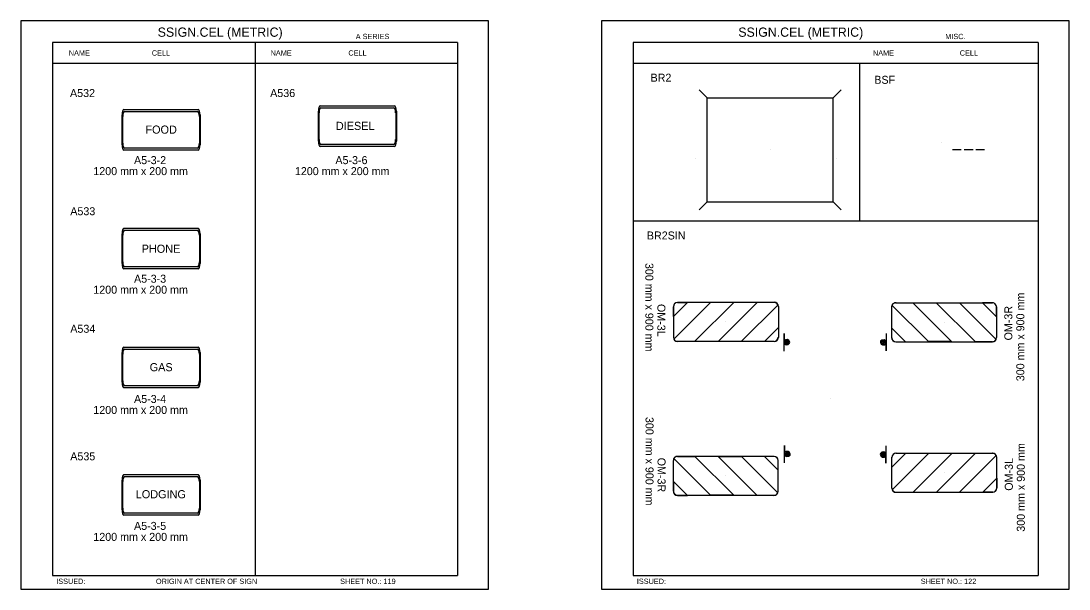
# Model space of a CAD drawing. Extents: x -12 to 6962, y -3756 to 679.
# Drawn here: x 237.8 to 630.7, y -2779.8 to -2566.7 of the extents above; entities that cross this region are included whole.
import ezdxf

# ---------------------------------------------------------------- set-up
doc = ezdxf.new("R2010")
doc.units = 0
for name, color, linetype in [('Level 1', 7, 'Continuous'), ('Level 2', 7, 'Continuous'), ('Level 3', 7, 'Continuous'), ('Level 60', 7, 'Continuous')]:
    doc.layers.add(name, color=color, linetype=linetype)

msp = doc.modelspace()

# ---------------------------------------------------------------- linework, layer by layer
at = {"layer": 'Level 1'}
for p, q in [((401.39, -2574.77), (249.64, -2574.77)), ((249.64, -2574.77), (249.64, -2774.77)), ((325.51, -2574.77), (325.51, -2774.77)), ((401.39, -2574.77), (401.39, -2774.77)), ((619.06, -2574.77), (467.3, -2574.77)), ((467.3, -2574.77), (467.3, -2774.77)), ((619.06, -2574.77), (619.06, -2774.77)), ((401.39, -2582.69), (249.64, -2582.69)), ((619.06, -2582.69), (467.3, -2582.69)), ((552.07, -2582.69), (552.07, -2641.89)), ((494.96, -2595.58), (491.98, -2592.6)), ((542.3, -2595.58), (545.28, -2592.6)), ((494.96, -2634.61), (494.96, -2595.58)), ((494.96, -2595.58), (542.3, -2595.58)), ((528.1, -2595.58), (538.37, -2595.58)), ((542.3, -2634.61), (542.3, -2595.58)), ((276.39, -2599.95), (304.18, -2599.95)), ((276.6, -2600.7), (303.97, -2600.7)), ((349.25, -2611.78), (349.25, -2600.61)), ((349.98, -2598.57), (377.78, -2598.57)), ((350.2, -2599.33), (377.56, -2599.33)), ((378.51, -2600.61), (378.51, -2611.78)), ((275.66, -2613.16), (275.66, -2601.98)), ((275.93, -2612.56), (275.93, -2602.58)), ((304.64, -2602.58), (304.64, -2612.56)), ((304.91, -2601.98), (304.91, -2613.16)), ((349.52, -2611.18), (349.52, -2601.21)), ((378.24, -2601.21), (378.24, -2611.18)), ((290.28, -2607.57), (290.28, -2607.57)), ((290.28, -2607.57), (290.28, -2607.57)), ((363.88, -2606.19), (363.88, -2606.19)), ((363.88, -2606.19), (363.88, -2606.19)), ((582.93, -2612.43), (582.93, -2612.43)), ((304.18, -2615.19), (276.39, -2615.19)), ((303.97, -2614.43), (276.6, -2614.43)), ((377.78, -2613.81), (349.98, -2613.81)), ((377.56, -2613.06), (350.2, -2613.06)), ((518.68, -2615), (518.68, -2615)), ((587.06, -2614.97), (590.23, -2614.97)), ((591.32, -2614.97), (594.76, -2614.97)), ((595.8, -2614.97), (598.97, -2614.97)), ((490.52, -2618.45), (490.52, -2618.45)), ((543.45, -2618.45), (543.45, -2618.45)), ((491.98, -2637.59), (494.96, -2634.61)), ((494.96, -2634.61), (542.3, -2634.61)), ((528.1, -2634.61), (539.68, -2634.61)), ((545.28, -2637.59), (542.3, -2634.61)), ((619.06, -2641.89), (467.3, -2641.89)), ((275.66, -2657.71), (275.66, -2646.53)), ((275.93, -2657.11), (275.93, -2647.13)), ((276.39, -2644.5), (304.18, -2644.5)), ((276.6, -2645.25), (303.97, -2645.25)), ((304.64, -2647.13), (304.64, -2657.11)), ((304.91, -2646.53), (304.91, -2657.71)), ((290.28, -2652.12), (290.28, -2652.12)), ((290.28, -2652.12), (290.28, -2652.12)), ((304.18, -2659.74), (276.39, -2659.74)), ((303.97, -2658.99), (276.6, -2658.99)), ((487.65, -2672.29), (482.38, -2677.55)), ((482.38, -2673.85), (482.38, -2685.35)), ((482.38, -2677.55), (482.38, -2673.91)), ((496.29, -2672.35), (482.58, -2686.07)), ((483.88, -2672.29), (487.65, -2672.29)), ((520.28, -2672.29), (483.94, -2672.29)), ((490.44, -2686.85), (505, -2672.35)), ((505, -2672.35), (496.29, -2672.35)), ((513.71, -2672.35), (499.22, -2686.85)), ((507.93, -2686.85), (521.58, -2673.2)), ((520.02, -2672.29), (513.71, -2672.35)), ((521.71, -2673.85), (521.71, -2685.35)), ((564.18, -2674), (564.18, -2685.51)), ((577.96, -2687), (564.31, -2673.35)), ((565.61, -2672.44), (601.95, -2672.44)), ((565.87, -2672.44), (572.18, -2672.51)), ((572.18, -2672.51), (586.67, -2687)), ((580.89, -2672.51), (589.6, -2672.51)), ((595.45, -2687), (580.89, -2672.51)), ((589.6, -2672.51), (603.31, -2686.22)), ((598.24, -2672.44), (603.51, -2677.71)), ((602.01, -2672.44), (598.24, -2672.44)), ((603.51, -2674), (603.51, -2685.51)), ((603.51, -2677.71), (603.51, -2674.07)), ((502.08, -2679.6), (502.08, -2679.6)), ((583.82, -2679.75), (583.82, -2679.75)), ((516.51, -2686.91), (521.71, -2681.71)), ((521.71, -2681.71), (521.71, -2685.35)), ((569.38, -2687.07), (564.18, -2681.87)), ((564.18, -2681.87), (564.18, -2685.51)), ((483.88, -2686.91), (490.44, -2686.85)), ((520.15, -2686.91), (483.94, -2686.91)), ((499.22, -2686.85), (507.93, -2686.85)), ((520.08, -2686.91), (516.51, -2686.91)), ((521.71, -2685.35), (521.71, -2685.42)), ((564.18, -2685.51), (564.18, -2685.57)), ((565.74, -2687.07), (601.95, -2687.07)), ((565.81, -2687.07), (569.38, -2687.07)), ((586.67, -2687), (577.96, -2687)), ((602.01, -2687.07), (595.45, -2687)), ((275.66, -2702.26), (275.66, -2691.08)), ((276.39, -2689.05), (304.18, -2689.05)), ((276.6, -2689.81), (303.97, -2689.81)), ((304.91, -2691.08), (304.91, -2702.26)), ((275.93, -2701.66), (275.93, -2691.68)), ((304.64, -2691.68), (304.64, -2701.66)), ((290.28, -2696.67), (290.28, -2696.67)), ((290.28, -2696.67), (290.28, -2696.67)), ((304.18, -2704.29), (276.39, -2704.29)), ((303.97, -2703.54), (276.6, -2703.54)), ((541.15, -2708.25), (541.15, -2708.25)), ((483.84, -2730.06), (490.4, -2730.12)), ((520.11, -2730.06), (483.9, -2730.06)), ((490.4, -2730.12), (504.96, -2744.62)), ((513.67, -2744.62), (499.18, -2730.12)), ((499.18, -2730.12), (507.89, -2730.12)), ((507.89, -2730.12), (521.54, -2743.78)), ((520.04, -2730.06), (516.47, -2730.06)), ((516.47, -2730.06), (521.67, -2735.26)), ((569.45, -2728.9), (564.25, -2734.1)), ((564.25, -2730.46), (564.25, -2730.4)), ((564.25, -2741.97), (564.25, -2730.46)), ((564.25, -2734.1), (564.25, -2730.46)), ((578.03, -2728.97), (564.38, -2742.62)), ((565.81, -2728.9), (602.02, -2728.9)), ((565.88, -2728.9), (569.45, -2728.9)), ((572.25, -2743.46), (586.74, -2728.97)), ((586.74, -2728.97), (578.03, -2728.97)), ((595.52, -2728.97), (580.96, -2743.46)), ((589.67, -2743.46), (603.38, -2729.75)), ((602.08, -2728.9), (595.52, -2728.97)), ((603.58, -2741.97), (603.58, -2730.46)), ((482.34, -2743.12), (482.34, -2731.62)), ((496.25, -2744.62), (482.54, -2730.91)), ((521.67, -2731.62), (521.67, -2731.55)), ((521.67, -2743.12), (521.67, -2731.62)), ((521.67, -2735.26), (521.67, -2731.62)), ((276.39, -2736.9), (304.18, -2736.9)), ((276.6, -2737.66), (303.97, -2737.66)), ((502.03, -2737.37), (502.03, -2737.37)), ((583.88, -2736.22), (583.88, -2736.22)), ((598.31, -2743.53), (603.58, -2738.26)), ((603.58, -2738.26), (603.58, -2741.9)), ((275.66, -2750.11), (275.66, -2738.93)), ((275.93, -2749.51), (275.93, -2739.54)), ((304.64, -2739.54), (304.64, -2749.51)), ((304.91, -2738.93), (304.91, -2750.11)), ((487.61, -2744.68), (482.34, -2739.42)), ((482.34, -2739.42), (482.34, -2743.06)), ((290.28, -2744.52), (290.28, -2744.52)), ((290.28, -2744.52), (290.28, -2744.52)), ((483.84, -2744.68), (487.61, -2744.68)), ((520.24, -2744.68), (483.9, -2744.68)), ((504.96, -2744.62), (496.25, -2744.62)), ((519.98, -2744.68), (513.67, -2744.62)), ((565.68, -2743.53), (602.02, -2743.53)), ((565.94, -2743.53), (572.25, -2743.46)), ((580.96, -2743.46), (589.67, -2743.46)), ((602.08, -2743.53), (598.31, -2743.53)), ((304.18, -2752.14), (276.39, -2752.14)), ((303.97, -2751.39), (276.6, -2751.39)), ((249.64, -2774.77), (401.39, -2774.77)), ((467.3, -2774.77), (619.06, -2774.77))]:
    msp.add_line(p, q, dxfattribs=at)
for centre, radius, start, end in [((483.94, -2673.85), 1.56, 90, 180), ((483.93, -2673.84), 1.53, 93.0907, 183.0907), ((520.11, -2673.95), 1.64, 26.6664, 93.2943), ((520.12, -2673.86), 1.59, 0.5054, 90.5054), ((565.77, -2674.02), 1.59, 89.4946, 179.4946), ((565.78, -2674.11), 1.64, 86.7057, 153.3336), ((601.95, -2674.01), 1.56, 0, 90), ((601.96, -2674), 1.53, 356.9093, 86.9093), ((483.94, -2685.36), 1.56, 180, 270), ((483.88, -2685.43), 1.46, 206.4031, 269.2905), ((520.12, -2685.34), 1.57, 268.6953, 358.1007), ((520.15, -2685.36), 1.56, 270, 0), ((565.74, -2685.51), 1.56, 180, 270), ((565.77, -2685.49), 1.57, 181.8993, 271.3047), ((601.95, -2685.51), 1.56, 270, 0), ((602.01, -2685.59), 1.46, 270.7095, 333.5969), ((483.9, -2731.62), 1.56, 90, 180), ((483.84, -2731.54), 1.46, 90.7095, 153.5969), ((520.08, -2731.63), 1.57, 1.8993, 91.3047), ((520.11, -2731.62), 1.56, 0, 90), ((565.81, -2730.46), 1.56, 90, 180), ((565.84, -2730.48), 1.57, 88.6953, 178.1007), ((602.02, -2730.46), 1.56, 0, 90), ((602.08, -2730.38), 1.46, 26.4031, 89.2905), ((565.84, -2741.95), 1.59, 180.5054, 270.5054), ((565.85, -2741.86), 1.64, 206.6664, 273.2943), ((602.02, -2741.96), 1.56, 270, 0), ((602.03, -2741.98), 1.53, 273.0907, 3.0907), ((483.9, -2743.12), 1.56, 180, 270), ((483.89, -2743.13), 1.53, 176.9093, 266.9093), ((520.07, -2743.02), 1.64, 266.7057, 333.3336), ((520.08, -2743.11), 1.59, 269.4946, 359.4946)]:
    msp.add_arc(centre, radius, start, end, dxfattribs=at)
for centre, major_axis, start_param, end_param in [((276.39, -2601.98), (0, -2.03), 3.141593, 4.712389), ((276.6, -2602.58), (0, -1.88), 3.141593, 4.712389), ((303.97, -2602.58), (0, 1.88), 4.712389, 6.283185), ((304.18, -2601.98), (0, 2.03), 4.712389, 6.283185), ((349.98, -2600.61), (0, -2.03), 3.141593, 4.712389), ((350.2, -2601.21), (0, -1.88), 3.141593, 4.712389), ((377.56, -2601.21), (0, 1.88), 4.712389, 6.283185), ((377.78, -2600.61), (0, 2.03), 4.712389, 6.283185), ((276.6, -2612.56), (0, -1.88), 4.712389, 6.283185), ((303.97, -2612.56), (0, 1.88), 3.141593, 4.712389), ((349.98, -2611.78), (0, -2.03), 4.712389, 6.283185), ((350.2, -2611.18), (0, -1.88), 4.712389, 6.283185), ((377.56, -2611.18), (0, 1.88), 3.141593, 4.712389), ((377.78, -2611.78), (0, 2.03), 3.141593, 4.712389), ((276.39, -2613.16), (0, -2.03), 4.712389, 6.283185), ((304.18, -2613.16), (0, 2.03), 3.141593, 4.712389), ((276.39, -2646.53), (0, -2.03), 3.141593, 4.712389), ((276.6, -2647.13), (0, -1.88), 3.141593, 4.712389), ((303.97, -2647.13), (0, 1.88), 4.712389, 6.283185), ((304.18, -2646.53), (0, 2.03), 4.712389, 6.283185), ((276.39, -2657.71), (0, -2.03), 4.712389, 6.283185), ((276.6, -2657.11), (0, -1.88), 4.712389, 6.283185), ((303.97, -2657.11), (0, 1.88), 3.141593, 4.712389), ((304.18, -2657.71), (0, 2.03), 3.141593, 4.712389), ((276.39, -2691.08), (0, -2.03), 3.141593, 4.712389), ((276.6, -2691.68), (0, -1.88), 3.141593, 4.712389), ((303.97, -2691.68), (0, 1.88), 4.712389, 6.283185), ((304.18, -2691.08), (0, 2.03), 4.712389, 6.283185), ((276.39, -2702.26), (0, -2.03), 4.712389, 6.283185), ((276.6, -2701.66), (0, -1.88), 4.712389, 6.283185), ((303.97, -2701.66), (0, 1.88), 3.141593, 4.712389), ((304.18, -2702.26), (0, 2.03), 3.141593, 4.712389), ((276.39, -2738.93), (0, -2.03), 3.141593, 4.712389), ((276.6, -2739.54), (0, -1.88), 3.141593, 4.712389), ((303.97, -2739.54), (0, 1.88), 4.712389, 6.283185), ((304.18, -2738.93), (0, 2.03), 4.712389, 6.283185), ((276.39, -2750.11), (0, -2.03), 4.712389, 6.283185), ((276.6, -2749.51), (0, -1.88), 4.712389, 6.283185), ((303.97, -2749.51), (0, 1.88), 3.141593, 4.712389), ((304.18, -2750.11), (0, 2.03), 3.141593, 4.712389)]:
    msp.add_ellipse(centre, major_axis=major_axis, ratio=0.36, start_param=start_param, end_param=end_param, dxfattribs=at)
at = {"layer": 'Level 2'}
for points in [[(523.87, -2690.54), (523.87, -2684.02), (523.87, -2687.18), (524.11, -2687.84), (524.62, -2688.2), (525.4, -2688.08), (525.94, -2687.65), (525.98, -2687.26), (525.67, -2686.6), (525.16, -2686.24), (524.42, -2686.28), (523.99, -2686.71), (524.11, -2687.41), (524.73, -2687.92), (525.24, -2687.77), (525.59, -2687.45), (525.4, -2686.79), (524.77, -2686.52), (524.42, -2686.91), (524.42, -2687.41), (524.73, -2687.61), (525.12, -2687.57), (525.16, -2687.22), (524.93, -2687.02), (524.69, -2687.02), (524.62, -2687.26), (524.85, -2687.3)], [(562.08, -2683.98), (562.08, -2690.5), (562.08, -2687.34), (561.85, -2686.67), (561.34, -2686.32), (560.56, -2686.44), (560.02, -2686.87), (559.98, -2687.26), (560.29, -2687.92), (560.8, -2688.27), (561.54, -2688.23), (561.97, -2687.8), (561.85, -2687.1), (561.23, -2686.6), (560.72, -2686.75), (560.37, -2687.06), (560.56, -2687.73), (561.19, -2688), (561.54, -2687.61), (561.54, -2687.1), (561.23, -2686.91), (560.84, -2686.95), (560.8, -2687.3), (561.03, -2687.49), (561.26, -2687.49), (561.34, -2687.26), (561.11, -2687.22)], [(524.05, -2732.48), (524.05, -2725.97), (524.05, -2729.13), (524.29, -2729.79), (524.79, -2730.14), (525.57, -2730.03), (526.12, -2729.6), (526.16, -2729.21), (525.85, -2728.54), (525.34, -2728.19), (524.6, -2728.23), (524.17, -2728.66), (524.29, -2729.36), (524.91, -2729.87), (525.42, -2729.71), (525.77, -2729.4), (525.57, -2728.74), (524.95, -2728.47), (524.6, -2728.86), (524.6, -2729.36), (524.91, -2729.56), (525.3, -2729.52), (525.34, -2729.17), (525.1, -2728.97), (524.87, -2728.97), (524.79, -2729.21), (525.03, -2729.25)], [(562.02, -2726.04), (562.02, -2732.56), (562.02, -2729.4), (561.79, -2728.74), (561.28, -2728.38), (560.5, -2728.5), (559.96, -2728.93), (559.92, -2729.32), (560.23, -2729.98), (560.74, -2730.33), (561.48, -2730.3), (561.91, -2729.87), (561.79, -2729.16), (561.17, -2728.66), (560.66, -2728.81), (560.31, -2729.13), (560.5, -2729.79), (561.13, -2730.06), (561.48, -2729.67), (561.48, -2729.16), (561.17, -2728.97), (560.78, -2729.01), (560.74, -2729.36), (560.97, -2729.55), (561.21, -2729.55), (561.28, -2729.32), (561.05, -2729.28)]]:
    msp.add_lwpolyline(points, dxfattribs=at)
at = {"layer": 'Level 60'}
for points in [[(237.76, -2779.82), (413.02, -2779.82), (413.02, -2566.73), (237.76, -2566.73)], [(455.43, -2779.82), (630.69, -2779.82), (630.69, -2566.73), (455.43, -2566.73)]]:
    msp.add_lwpolyline(points, close=True, dxfattribs=at)

# ---------------------------------------------------------------- texts
at = {"layer": 'Level 1'}
for s, p in [('DIESEL', (355.82, -2607.61)), ('FOOD', (284.43, -2609.01)), ('PHONE', (283.01, -2653.69)), ('GAS', (286.02, -2698.13)), ('LODGING', (280.79, -2745.78))]:
    msp.add_text(s, height=3.049, dxfattribs=at).set_placement(p)
at = {"layer": 'Level 2'}
for s, p in [('A532', (256.15, -2595.27)), ('A536', (331.19, -2595.27)), ('A533', (256.25, -2639.61)), ('A534', (256.25, -2683.69)), ('A535', (256.25, -2731.53))]:
    msp.add_text(s, height=3, dxfattribs=at).set_placement(p)
at = {"layer": 'Level 3'}
for s, height, p in [('SSIGN.CEL (METRIC)', 3.4642, (289.02, -2572.66)), ('SSIGN.CEL (METRIC)', 3.4642, (506.69, -2572.66)), ('A SERIES', 1.979, (363.27, -2573.54)), ('MISC.', 1.979, (584.28, -2573.54)), ('NAME', 1.98, (255.69, -2579.73)), ('CELL', 1.98, (286.81, -2579.73)), ('NAME', 1.98, (331.35, -2579.73)), ('CELL', 1.98, (360.51, -2579.73)), ('NAME', 1.98, (557.18, -2579.73)), ('CELL', 1.98, (589.72, -2579.73)), ('BR2', 3, (473.8, -2589.51)), ('BSF', 3, (557.68, -2590.3)), ('A5-3-2', 3, (280.15, -2620.44)), ('A5-3-6', 3, (355.64, -2620.44)), ('1200 mm x 200 mm', 3, (264.89, -2624.56)), ('1200 mm x 200 mm', 3, (340.46, -2624.56)), ('BR2SIN', 3, (472.41, -2648.7)), ('A5-3-3', 3, (280.15, -2664.92)), ('1200 mm x 200 mm', 3, (264.89, -2669.04)), ('A5-3-4', 3, (280.15, -2710.02)), ('1200 mm x 200 mm', 3, (264.89, -2714.14)), ('A5-3-5', 3, (280.15, -2757.63)), ('1200 mm x 200 mm', 3, (264.89, -2761.75)), ('ISSUED:', 1.98, (250.98, -2777.9)), ('ORIGIN AT CENTER OF SIGN', 1.9795, (288.36, -2777.9)), ('SHEET NO.: 119', 1.9795, (357.41, -2777.9)), ('ISSUED:', 1.98, (468.65, -2777.9)), ('SHEET NO.: 122', 1.9795, (575.09, -2777.9))]:
    msp.add_text(s, height=height, dxfattribs=at).set_placement(p)
for s, rotation, p in [('300 mm x 900 mm', 270, (471.85, -2657.5)), ('300 mm x 900 mm', 90, (613.93, -2701.86)), ('OM-3L', 270, (476.35, -2672.88)), ('OM-3R', 90, (609.43, -2686.56)), ('300 mm x 900 mm', 270, (471.92, -2715.27)), ('300 mm x 900 mm', 90, (614.11, -2758.32)), ('OM-3R', 270, (476.42, -2730.57)), ('OM-3L', 90, (609.61, -2742.94))]:
    msp.add_text(s, height=3, rotation=rotation, dxfattribs=at).set_placement(p)

doc.saveas('drawing.dxf')
